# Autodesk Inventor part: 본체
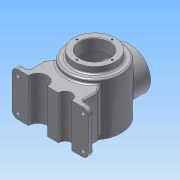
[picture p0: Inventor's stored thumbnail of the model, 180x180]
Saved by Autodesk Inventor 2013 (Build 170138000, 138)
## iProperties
Created: 2018-08
Part Number: 본체
Material: 알루미늄 6061
Document SubType Name: Modeling
Designer: Administrator
Density: 2.71 g/cm^3
Mass: 1886.06 g
Surface Area: 1087.45 cm^2
Volume: 695.964 cm^3
Author: Administrator
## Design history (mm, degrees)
sketch "스케치1"
  geometry: C1 r 50 at (0, 0); 1 further point
  constraints: 1 centre point, 1 coincident
  dimensions: "d0" = 100 diameter of C1
extrude "돌출1" new body sketch "스케치1" stored distance "d1" = 108; taper "d2" = 0 deg
sketch "스케치2"
  geometry: L1 (-50, -54)-(50, -54) reference; L2 (116, 62)-(-116, 62); L3 (50, 54)-(-50, 54) reference; A1 r 116 centre (0, 62) between (-116, 62) and (116, 62); 1 further point
  constraints: 2 end point, 2 point on circle, 1 centre point, 1 parallel, 1 tangent, 1 vertical alignment
  dimensions: "d4" = 232 diameter of A1; "d129" = 108 distance between parallel lines of L1 L3 (derived)
revolve "회전1" sketch "스케치2" stored, may be unused: angle "d5" = 90 deg
node "작업 평면1"
sketch "스케치3"
  geometry: L1 (-70, -82)-(70, -82); L2 (70, -82)-(70, -72); L3 (70, -72)-(-70, -72); L4 (-70, -72)-(-70, -82); 2 further points
  constraints: 8 end point, 2 parallel, 1 horizontal, 1 midpoint, 1 perpendicular, 1 vertical alignment
  dimensions: "d26" = 140 distance of L3.end L2.end; "d27" = 10 distance of L2.end L1.end; "d28" = 82 distance from line of L1 point (0, 0)
extrude "돌출2" join sketch "스케치3" distance "d29" = 80; taper "d30" = 0 deg
sketch "스케치4"
  geometry: L1 (70, -72)-(-70, -72) reference; L2 (-56.207, -85.689)-(32.46, -85.689); L3 (-50, -43.437)-(-29.918, -14.758); L4 (-50, -72)-(-50, -43.437); L5 (50, -43.437)-(29.918, -14.758); L6 (70, -72)-(139.88, -72); L7 (50, -72)-(50, -43.437); L8 (29.918, -14.758)-(-29.918, -14.758); L9 (-50, -72)-(50, -72); 1 further point
  constraints: 16 end point, 3 perpendicular, 2 horizontal, 2 point on line, 1 collinear
  dimensions: "d34" = 20 distance from line of L4 L1.end; "d35" = 125 deg angle of L6 L5; "d36" = 20 distance from line of L1.start L7; "d37" = 28.67954 vertical distance of L5.start L5.end; "d38" = 28.67954 vertical distance of L3.start L3.end; "d39" = 59.83674 distance of L5.end L3.end; "d40" = 28.56296 distance from line of L1 L3.start
extrude "돌출3" join sketch "스케치4" distance "d41" = 80; taper "d42" = 0 deg
sketch "스케치5"
  geometry: C1 r 50 at (0, 0) reference; C2 r 38 at (0, 0)
  constraints: 1 centre point, 1 coincident
  dimensions: "d43" = 76 diameter of C2
extrude "돌출4" join sketch "스케치5" distance "d44" = 12; taper "d45" = 0 deg
sketch "스케치6"
  geometry: C1 r 38 at (0, 0) reference; C2 r 27 at (0, 0)
  constraints: 1 centre point, 1 coincident
  dimensions: "d46" = 54 diameter of C2
extrude "돌출5" cut sketch "스케치6" distance "d47" = 22; taper "d48" = 0 deg
sketch "스케치7"
  geometry: L1 (0, 44)-(0, -59.052); L2 (-27, 44)-(27, 44) reference; L3 (0, 44)-(40, 44); L4 (40, 44)-(40, -36.163); A1 r 116 centre (0, 62) between (-50, -42.671) and (50, -42.671) reference; A2 r 106 centre (0, 62) between (0, -44) and (40, -36.163); 1 further point
  constraints: 6 end point, 2 point on circle, 2 point on line, 1 centre point, 1 midpoint, 1 perpendicular, 1 vertical
  dimensions: "d49" = 10 radial gap between concentric circles of A1 A2; "d51" = 80 diameter of L4 L1
revolve "회전2" sketch "스케치7" stored, may be unused: angle "d52" = 90 deg
node "작업 평면2"
sketch "스케치8"
  geometry: L1 (120, 8)-(20, 8) reference; L2 (0, 0)-(0, -80) reference; C1 r 38 at (70, -42); 1 further point
  constraints: 1 centre point
  dimensions: "d54" = 76 diameter of C1; "d55" = 50 distance from line of L1 C1.centre; "d56" = 70 distance from line of L2 C1.centre
extrude "돌출6" join sketch "스케치8" stored distance "d57" = 70 (= d56); taper "d58" = 0 deg
sketch "스케치9"
  geometry: C1 r 38 at (0, 0) reference; C2 r 27 at (0, 0); 1 further point
  constraints: 1 centre point, 1 coincident
  dimensions: "d59" = 54 diameter of C2
extrude "돌출7" cut sketch "스케치9" stored distance "d60" = 70 (= d56); taper "d61" = 0 deg
sketch "스케치10"
  geometry: L1 (-70, -82)-(70, -82) reference; C1 r 17.5 at (-22.5, -82); C2 r 12.5 at (27.5, -82); A1 r 50 centre (0, 0) between (-40.304, -29.59) and (40.304, -29.59) reference
  constraints: 2 centre point, 2 point on line
  dimensions: "d62" = 35 diameter of C1; "d63" = 25 diameter of C2; "d64" = 22.5 horizontal distance of A1.centre C1.centre; "d65" = 27.5 horizontal distance of C2.centre A1.centre
extrude "돌출8" cut sketch "스케치10" stored distance "d66" = 70 (= d56); taper "d67" = 0 deg
fillet "모깎기1" dims "d68" = 10
hole "구멍1" diameter "d71" = 8; stored, may be unused: countersink angle "d75" = 90 deg, drill point angle "d77" = 0 deg; dims "d69" = 10, "d70" = 10, "d72" = 6, "d73" = 4, "d74" = 2, "d76" = 8
hole "구멍2" diameter "d80" = 8; stored, may be unused: countersink angle "d84" = 90 deg, drill point angle "d86" = 0 deg; dims "d78" = 10, "d79" = 10, "d81" = 6, "d82" = 4, "d83" = 2, "d85" = 8
hole "구멍3" diameter "d89" = 8; stored, may be unused: countersink angle "d93" = 90 deg, drill point angle "d95" = 0 deg; dims "d87" = 10, "d88" = 10, "d90" = 6, "d91" = 4, "d92" = 2, "d94" = 8
hole "구멍4" diameter "d98" = 8; stored, may be unused: countersink angle "d102" = 90 deg, drill point angle "d104" = 0 deg; dims "d96" = 10, "d97" = 10, "d99" = 6, "d100" = 4, "d101" = 2, "d103" = 8
sketch "스케치11"
  geometry: C1 r 27 at (0, 0) reference; C2 r 38 at (0, 0) reference; A1 r 32.5 centre (0, 0) between (0, 32.5) and (0, -32.5); 3 further points
  constraints: 4 point on circle, 2 horizontal alignment, 2 vertical alignment, 1 centre point, 1 coincident
  dimensions: "d105" = 65 diameter of A1
hole "구멍5" sketch "스케치11" at (0, 32.5), (32.5, 0), (0, -32.5), (-32.5, 0) diameter "d106" = 3.242; stored, may be unused: countersink angle "d110" = 90 deg, drill point angle "d112" = 118 deg; dims "d107" = 8, "d108" = 4, "d109" = 2, "d111" = 10
sketch "스케치12"
  geometry: C1 r 27 at (0, 0) reference; C2 r 38 at (0, 0) reference; A1 r 32.5 centre (0, 0) between (0, 32.5) and (0, -32.5); 2 further points
  constraints: 4 point on circle, 2 horizontal alignment, 2 vertical alignment, 1 centre point, 1 coincident
  dimensions: "d113" = 65 diameter of A1
hole "구멍6" sketch "스케치12" at (0, 32.5), (0, -32.5), (32.5, 0), (-32.5, 0) diameter "d114" = 3.242; stored, may be unused: countersink angle "d118" = 90 deg, drill point angle "d120" = 118 deg; dims "d115" = 8, "d116" = 4, "d117" = 2, "d119" = 10
node "작업 평면3"
sketch "스케치13"
  geometry: C1 r 32.5 at (0, 0); 1 further point
  constraints: 1 centre point, 1 coincident, 1 other
  dimensions: "d122" = 65 diameter of C1
feature "엠보싱1" sketch "스케치13" dims "d123" = 0.5, "d124" = 0
fillet "모깎기2" dims "d125" = 3
chamfer "모따기1" distance "d126" = 1; stored, may be unused: second distance "d127" = 2, angle "d128" = 45 deg
node "솔리드1"
other parameters: "d6" = -8, "d32" = 55 deg, "d53" = -147, "d121" = -108
